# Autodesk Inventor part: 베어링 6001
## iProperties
IsCustomPart: 0
Created: 2009-02
Part Number: 베어링 6001
Material: 강, 연강
Description: 깊은 그루브 볼 베어링
Document SubType Name: Modeling
Standard: KS B 2023
Designer: SeoGD™
Standards Organization: KS
Language: ko-KR
Size Designation: 6001 - 12 x 28 x 8
Categories: <MemberInstance><Categories><Category DisplayName="샤프트 부품" InternalName="7f7aeb1f-a693-4053-b835-cee3144e0d98" Mnemonic="SHFT"><Category DisplayName="베어링" Inter
Density: 1 g/cm^3
Author: SeoGD™
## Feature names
1. IDS_ARRAYBALL[SIMPL:T] [Circular Pattern]
